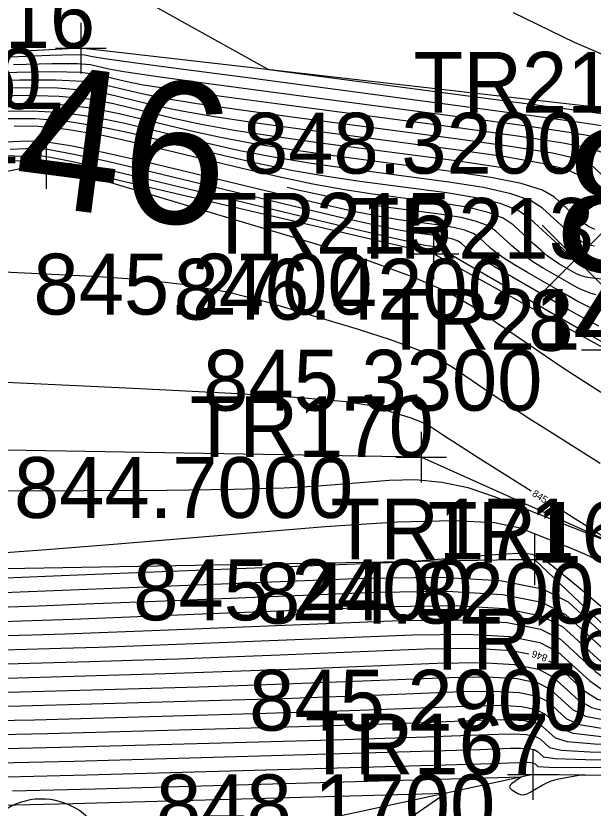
# Model space of a CAD drawing. Extents: x 1654928 to 1810050, y 486881 to 626330.
# Drawn here: x 1801337.91 to 1801349.3, y 489780.62 to 489796.25 of the extents above; entities that cross this region are included whole.
import ezdxf

# ---------------------------------------------------------------- set-up
doc = ezdxf.new("R2010")
doc.units = 0
for name, color, linetype in [('DR_X_Ditch', 7, 'Continuous'), ('DT_X_Contour_Major', 7, 'Continuous'), ('DT_X_Contour_Minor', 7, 'Continuous'), ('SV_X_Random_Point', 7, 'Continuous'), ('SV_X_Shot_Marker', 7, 'Continuous'), ('SV_X_Text_Elevation', 7, 'Continuous'), ('SV_X_Text_Name', 7, 'Continuous'), ('SV_X_Toe_of_Slope', 7, 'Continuous'), ('SV_X_Top_of_Bank', 7, 'Continuous'), ('VG_X_Cells', 7, 'Continuous')]:
    doc.layers.add(name, color=color, linetype=linetype)

msp = doc.modelspace()

# ---------------------------------------------------------------- linework, layer by layer
at = {"layer": 'DR_X_Ditch'}
msp.add_lwpolyline([(1801415.613, 489805.461), (1801399.12, 489798.656), (1801394.115, 489798.231), (1801381.169, 489793.34), (1801378.227, 489791.154), (1801376.864, 489788.486), (1801373.817, 489786.687), (1801350.547, 489785.463), (1801345.905, 489787.547), (1801327.981, 489787.847), (1801322.506, 489787.279)], dxfattribs=at)
at = {"layer": 'DT_X_Contour_Major'}
for points in [[(1801349.723, 489794.04), (1801349.121, 489794.135), (1801348.139, 489794.274), (1801346.777, 489794.457), (1801342.637, 489795.005), (1801341.272, 489795.186), (1801340.281, 489795.319), (1801339.664, 489795.404), (1801339.421, 489795.442), (1801339.272, 489795.478), (1801339.072, 489795.482), (1801338.583, 489795.469), (1801337.806, 489795.438)], [(1801347.859, 489793.184), (1801347.423, 489793.267), (1801346.546, 489793.396), (1801343.923, 489793.742), (1801343.005, 489793.87), (1801342.22, 489793.992), (1801341.568, 489794.109), (1801341.047, 489794.221), (1801339.837, 489794.513), (1801339.342, 489794.604), (1801338.767, 489794.659), (1801338.11, 489794.677), (1801337.372, 489794.658)], [(1801349.358, 489790.75), (1801349.263, 489790.771), (1801349.141, 489790.817), (1801348.992, 489790.888), (1801348.817, 489790.985), (1801348.312, 489791.276), (1801348.131, 489791.385), (1801347.969, 489791.495), (1801347.824, 489791.604), (1801347.697, 489791.713), (1801347.382, 489792.005), (1801347.227, 489792.108), (1801346.998, 489792.197), (1801346.694, 489792.272), (1801346.316, 489792.334), (1801345.209, 489792.48), (1801344.739, 489792.554), (1801344.16, 489792.665), (1801343.472, 489792.814), (1801343.265, 489792.862)], [(1801336.718, 489791.247), (1801339.433, 489791.119), (1801340.409, 489791.052), (1801341.302, 489790.945), (1801342.112, 489790.799), (1801342.838, 489790.614), (1801344.663, 489790.068), (1801345.293, 489789.868), (1801345.812, 489789.678), (1801346.22, 489789.498), (1801346.518, 489789.327), (1801347.165, 489788.886), (1801347.425, 489788.711), (1801347.721, 489788.517), (1801348.051, 489788.304), (1801348.416, 489788.072), (1801349.437, 489787.428)], [(1801355.714, 489785.207), (1801353.704, 489785.061), (1801352.39, 489784.954), (1801351.771, 489784.885), (1801351.048, 489784.753), (1801350.792, 489784.726), (1801350.567, 489784.742), (1801350.373, 489784.802), (1801350.209, 489784.906), (1801349.814, 489785.24), (1801349.639, 489785.367), (1801349.413, 489785.498), (1801349.136, 489785.633), (1801348.806, 489785.771), (1801347.859, 489786.145), (1801347.352, 489786.252), (1801346.543, 489786.291), (1801345.431, 489786.264), (1801344.016, 489786.169), (1801339.839, 489785.826), (1801338.431, 489785.714), (1801337.34, 489785.634)], [(1801336.723, 489784), (1801338.226, 489784.042), (1801338.884, 489784.062), (1801339.731, 489784.092), (1801340.765, 489784.131), (1801345.501, 489784.322), (1801346.686, 489784.339), (1801347.606, 489784.283), (1801348.262, 489784.154), (1801348.654, 489783.953), (1801349.346, 489783.319), (1801349.627, 489783.111), (1801349.95, 489782.964), (1801350.315, 489782.878), (1801350.723, 489782.853), (1801351.867, 489782.865), (1801352.39, 489782.865), (1801353.1, 489782.855), (1801353.998, 489782.836), (1801355.084, 489782.808)], [(1801336.934, 489782.622), (1801338.017, 489782.639), (1801342.183, 489782.757), (1801343.169, 489782.788), (1801344.045, 489782.818), (1801344.81, 489782.847), (1801346.704, 489782.924), (1801347.343, 489782.933), (1801347.839, 489782.903), (1801348.193, 489782.833), (1801348.404, 489782.725), (1801348.777, 489782.383), (1801349.029, 489782.272), (1801349.504, 489782.196), (1801350.202, 489782.155), (1801351.123, 489782.149), (1801353.878, 489782.179), (1801354.873, 489782.186), (1801355.79, 489782.186)], [(1801337.742, 489781.243), (1801339.312, 489781.279), (1801347.324, 489781.505), (1801347.632, 489781.515), (1801347.907, 489781.526), (1801348, 489781.527), (1801348.072, 489781.523), (1801348.123, 489781.513), (1801348.154, 489781.497), (1801348.208, 489781.447), (1801348.431, 489781.433), (1801349.057, 489781.428), (1801350.088, 489781.432), (1801351.523, 489781.446), (1801355.889, 489781.493)]]:
    msp.add_lwpolyline(points, dxfattribs=at)
at = {"layer": 'DT_X_Contour_Minor'}
for points in [[(1801355.691, 489793.524), (1801354.891, 489793.623), (1801352.455, 489793.925), (1801351.649, 489794.024), (1801351.059, 489794.095), (1801350.685, 489794.137), (1801350.526, 489794.151), (1801350.391, 489794.151), (1801350.345, 489794.151), (1801350.311, 489794.152), (1801350.286, 489794.152), (1801350.273, 489794.153), (1801350.25, 489794.155), (1801350.241, 489794.157), (1801350.232, 489794.162), (1801350.221, 489794.169), (1801350.21, 489794.179), (1801350.179, 489794.208), (1801350.032, 489794.235), (1801349.617, 489794.296), (1801348.933, 489794.39), (1801347.979, 489794.517), (1801342.902, 489795.188), (1801340.65, 489796.433)], [(1801355.223, 489795.998), (1801354.882, 489796.013), (1801354.491, 489796), (1801354.048, 489795.961), (1801352.798, 489795.82), (1801352.361, 489795.759), (1801351.987, 489795.682), (1801351.676, 489795.588), (1801351.428, 489795.478), (1801350.852, 489795.164), (1801350.494, 489795.148), (1801349.854, 489795.333), (1801348.932, 489795.722), (1801347.727, 489796.312)], [(1801349.486, 489793.836), (1801348.914, 489793.936), (1801347.996, 489794.073), (1801346.731, 489794.245), (1801342.894, 489794.752), (1801341.619, 489794.923), (1801340.669, 489795.054), (1801340.044, 489795.145), (1801339.746, 489795.198), (1801339.385, 489795.285), (1801339.126, 489795.307), (1801338.62, 489795.307), (1801337.867, 489795.286)], [(1801349.475, 489793.552), (1801349.248, 489793.631), (1801348.707, 489793.737), (1801347.853, 489793.871), (1801346.685, 489794.033), (1801343.152, 489794.5), (1801341.965, 489794.659), (1801341.057, 489794.788), (1801340.425, 489794.886), (1801340.071, 489794.954), (1801339.498, 489795.092), (1801339.18, 489795.131), (1801338.657, 489795.145), (1801337.928, 489795.133), (1801336.993, 489795.097)], [(1801349.481, 489793.111), (1801349.241, 489793.333), (1801349.011, 489793.426), (1801348.5, 489793.539), (1801347.71, 489793.67), (1801346.639, 489793.82), (1801343.409, 489794.247), (1801342.312, 489794.396), (1801341.444, 489794.523), (1801340.806, 489794.627), (1801340.397, 489794.709), (1801339.611, 489794.899), (1801339.234, 489794.955), (1801338.693, 489794.983), (1801337.988, 489794.981), (1801337.119, 489794.95)], [(1801349.405, 489792.754), (1801349.299, 489792.844), (1801349.007, 489793.115), (1801348.774, 489793.222), (1801348.294, 489793.34), (1801347.566, 489793.468), (1801346.592, 489793.608), (1801343.666, 489793.995), (1801342.659, 489794.133), (1801341.832, 489794.257), (1801341.187, 489794.368), (1801340.722, 489794.465), (1801339.724, 489794.706), (1801339.288, 489794.78), (1801338.73, 489794.821), (1801338.049, 489794.829), (1801337.246, 489794.804)], [(1801349.333, 489792.039), (1801349.211, 489792.097), (1801349.078, 489792.188), (1801348.934, 489792.31), (1801348.538, 489792.677), (1801348.299, 489792.813), (1801347.88, 489792.942), (1801347.28, 489793.065), (1801346.5, 489793.183), (1801344.18, 489793.49), (1801343.352, 489793.607), (1801342.608, 489793.727), (1801341.949, 489793.85), (1801341.373, 489793.977), (1801339.95, 489794.32), (1801339.396, 489794.429), (1801338.803, 489794.497), (1801338.171, 489794.524), (1801337.499, 489794.512)], [(1801349.329, 489791.706), (1801349.203, 489791.736), (1801349.065, 489791.802), (1801348.915, 489791.905), (1801348.752, 489792.043), (1801348.303, 489792.459), (1801348.062, 489792.608), (1801347.673, 489792.743), (1801347.137, 489792.864), (1801346.454, 489792.971), (1801344.437, 489793.237), (1801343.699, 489793.343), (1801342.996, 489793.461), (1801342.329, 489793.591), (1801341.698, 489793.733), (1801340.063, 489794.127), (1801339.45, 489794.253), (1801338.84, 489794.335), (1801338.232, 489794.372), (1801337.625, 489794.365)], [(1801349.578, 489791.363), (1801349.231, 489791.398), (1801349.117, 489791.41), (1801349.032, 489791.421), (1801348.977, 489791.429), (1801348.953, 489791.435), (1801348.929, 489791.449), (1801348.898, 489791.475), (1801348.824, 489791.541), (1801348.707, 489791.649), (1801348.546, 489791.798), (1801348.059, 489792.25), (1801347.818, 489792.409), (1801347.463, 489792.546), (1801346.993, 489792.663), (1801346.408, 489792.759), (1801344.695, 489792.985), (1801344.046, 489793.08), (1801343.384, 489793.196), (1801342.71, 489793.332), (1801342.023, 489793.489), (1801340.175, 489793.934), (1801339.504, 489794.077), (1801338.877, 489794.172), (1801338.293, 489794.22), (1801337.752, 489794.219)], [(1801349.577, 489791.045), (1801349.295, 489791.074), (1801349.19, 489791.09), (1801349.087, 489791.119), (1801348.985, 489791.158), (1801348.885, 489791.21), (1801348.62, 489791.362), (1801348.515, 489791.43), (1801348.396, 489791.518), (1801348.265, 489791.627), (1801348.121, 489791.756), (1801347.72, 489792.128), (1801347.523, 489792.258), (1801347.23, 489792.372), (1801346.844, 489792.468), (1801346.362, 489792.546), (1801344.952, 489792.733), (1801344.392, 489792.817), (1801343.772, 489792.931), (1801343.091, 489793.073), (1801342.349, 489793.245), (1801340.288, 489793.741), (1801339.558, 489793.902), (1801338.913, 489794.01), (1801338.353, 489794.067), (1801337.879, 489794.073)], [(1801349.337, 489790.451), (1801349.196, 489790.515), (1801349, 489790.618), (1801348.748, 489790.76), (1801348.003, 489791.19), (1801347.748, 489791.341), (1801347.541, 489791.471), (1801347.382, 489791.581), (1801347.272, 489791.671), (1801347.044, 489791.883), (1801346.931, 489791.957), (1801346.765, 489792.022), (1801346.544, 489792.077), (1801346.27, 489792.121), (1801345.466, 489792.228), (1801345.086, 489792.291), (1801344.548, 489792.4), (1801343.853, 489792.555), (1801342.999, 489792.757), (1801340.514, 489793.356), (1801339.666, 489793.551), (1801338.987, 489793.686), (1801338.475, 489793.763), (1801338.132, 489793.78), (1801337.44, 489793.747)], [(1801349.41, 489790.131), (1801349.251, 489790.213), (1801349.007, 489790.347), (1801348.68, 489790.534), (1801347.694, 489791.103), (1801347.364, 489791.296), (1801347.113, 489791.448), (1801346.941, 489791.559), (1801346.848, 489791.629), (1801346.706, 489791.761), (1801346.636, 489791.807), (1801346.532, 489791.847), (1801346.395, 489791.881), (1801346.224, 489791.909), (1801345.723, 489791.975), (1801345.433, 489792.027), (1801344.936, 489792.134), (1801344.233, 489792.296), (1801343.325, 489792.512), (1801340.627, 489793.163), (1801339.72, 489793.375), (1801339.023, 489793.524), (1801338.536, 489793.611), (1801338.258, 489793.634), (1801337.797, 489793.612)], [(1801349.483, 489789.811), (1801349.015, 489790.077), (1801346.98, 489791.251), (1801346.685, 489791.424), (1801346.499, 489791.536), (1801346.423, 489791.586), (1801346.367, 489791.638), (1801346.34, 489791.656), (1801346.299, 489791.672), (1801346.245, 489791.686), (1801346.178, 489791.697), (1801345.98, 489791.723), (1801345.779, 489791.764), (1801345.324, 489791.869), (1801344.614, 489792.037), (1801340.74, 489792.97), (1801339.774, 489793.199), (1801339.06, 489793.362), (1801338.597, 489793.458), (1801338.385, 489793.488), (1801338.154, 489793.477), (1801338.011, 489793.477), (1801337.754, 489793.487)], [(1801364.304, 489787.262), (1801363.958, 489787.248), (1801358.689, 489787.046), (1801356.868, 489787.012), (1801355.356, 489787.06), (1801354.154, 489787.191), (1801353.262, 489787.404), (1801351.295, 489788.083), (1801350.63, 489788.318), (1801350.113, 489788.513), (1801349.742, 489788.668), (1801349.518, 489788.783), (1801349.116, 489789.036), (1801348.933, 489789.154), (1801348.687, 489789.317), (1801348.378, 489789.525), (1801348.005, 489789.778), (1801346.927, 489790.514), (1801346.43, 489790.798), (1801345.75, 489791.099), (1801344.885, 489791.415), (1801343.836, 489791.749), (1801338.511, 489793.341), (1801332.343, 489792.068)], [(1801334.925, 489789.154), (1801340.354, 489788.898), (1801342.164, 489788.805), (1801343.522, 489788.72), (1801344.428, 489788.641), (1801344.883, 489788.569), (1801345.491, 489788.387), (1801345.701, 489788.321), (1801345.874, 489788.257), (1801346.01, 489788.197), (1801346.109, 489788.14), (1801346.325, 489787.993), (1801346.457, 489787.906), (1801346.693, 489787.755), (1801347.031, 489787.54), (1801348.078, 489786.88)], [(1801348.433, 489786.656), (1801349.773, 489785.81), (1801347.356, 489786.764), (1801346.837, 489786.938), (1801346.317, 489787.049), (1801345.797, 489787.099), (1801345.275, 489787.087), (1801343.883, 489786.973), (1801343.202, 489786.936), (1801342.202, 489786.908), (1801340.883, 489786.89), (1801339.247, 489786.882), (1801334.457, 489786.875)], [(1801337.714, 489785.165), (1801338.971, 489785.216), (1801345.61, 489785.484), (1801347.267, 489785.62), (1801347.585, 489785.642), (1801347.829, 489785.652), (1801348, 489785.648), (1801348.096, 489785.631), (1801348.254, 489785.569), (1801348.345, 489785.515), (1801348.499, 489785.401), (1801348.717, 489785.227), (1801348.998, 489784.992), (1801349.834, 489784.286), (1801350.179, 489784.067), (1801350.589, 489783.941), (1801351.065, 489783.907), (1801351.605, 489783.965), (1801353.131, 489784.243), (1801353.923, 489784.353), (1801355.153, 489784.477)], [(1801337.667, 489784.875), (1801344.779, 489785.161), (1801346.291, 489785.182), (1801347.466, 489785.111), (1801348.304, 489784.947), (1801348.804, 489784.69), (1801349.688, 489783.88), (1801349.986, 489783.615), (1801350.218, 489783.425), (1801350.384, 489783.312), (1801350.483, 489783.275), (1801350.75, 489783.276), (1801351.294, 489783.264), (1801352.463, 489783.231), (1801355.106, 489783.712)], [(1801337.565, 489784.585), (1801338.355, 489784.614), (1801339.453, 489784.657), (1801340.859, 489784.713), (1801345.019, 489784.881), (1801346.423, 489784.901), (1801347.513, 489784.835), (1801348.29, 489784.683), (1801348.754, 489784.444), (1801349.574, 489783.693), (1801349.866, 489783.447), (1801350.129, 489783.272), (1801350.361, 489783.167), (1801350.563, 489783.134), (1801351.063, 489783.139), (1801351.315, 489783.139), (1801351.696, 489783.132), (1801352.208, 489783.121), (1801352.848, 489783.104), (1801356.142, 489783.011)], [(1801337.654, 489784.305), (1801338.224, 489784.323), (1801339.043, 489784.353), (1801341.424, 489784.447), (1801345.26, 489784.602), (1801346.554, 489784.62), (1801347.56, 489784.559), (1801348.276, 489784.418), (1801348.704, 489784.198), (1801349.46, 489783.506), (1801349.747, 489783.279), (1801350.039, 489783.118), (1801350.338, 489783.023), (1801350.643, 489782.993), (1801351.465, 489783.002), (1801351.879, 489783.001), (1801352.507, 489782.991), (1801353.348, 489782.972), (1801354.403, 489782.943), (1801359.821, 489782.79)], [(1801336.981, 489783.728), (1801338.798, 489783.779), (1801339.544, 489783.801), (1801340.418, 489783.831), (1801341.421, 489783.869), (1801345.741, 489784.042), (1801346.817, 489784.058), (1801347.653, 489784.007), (1801348.248, 489783.89), (1801348.604, 489783.707), (1801349.232, 489783.132), (1801349.507, 489782.943), (1801349.861, 489782.811), (1801350.293, 489782.734), (1801350.803, 489782.712), (1801352.269, 489782.728), (1801352.886, 489782.729), (1801353.638, 489782.721), (1801354.525, 489782.704), (1801355.546, 489782.678)], [(1801337.24, 489783.456), (1801339.371, 489783.515), (1801340.204, 489783.54), (1801341.106, 489783.571), (1801342.077, 489783.606), (1801343.117, 489783.647), (1801345.982, 489783.763), (1801346.948, 489783.776), (1801347.699, 489783.731), (1801348.029, 489783.666)], [(1801348.422, 489783.53), (1801348.554, 489783.462), (1801349.119, 489782.944), (1801349.388, 489782.776), (1801349.771, 489782.657), (1801350.27, 489782.589), (1801350.883, 489782.571), (1801352.671, 489782.591), (1801353.383, 489782.593), (1801354.176, 489782.588), (1801355.051, 489782.573), (1801356.008, 489782.549)], [(1801337.499, 489783.183), (1801339.943, 489783.252), (1801340.864, 489783.279), (1801341.794, 489783.31), (1801342.733, 489783.343), (1801343.681, 489783.38), (1801346.223, 489783.483), (1801347.08, 489783.495), (1801347.746, 489783.455), (1801348.221, 489783.362), (1801348.504, 489783.216), (1801349.005, 489782.757), (1801349.268, 489782.608), (1801349.682, 489782.504), (1801350.247, 489782.444), (1801350.963, 489782.43), (1801353.074, 489782.453), (1801353.879, 489782.458), (1801354.714, 489782.454), (1801355.578, 489782.441)], [(1801337.758, 489782.911), (1801341.523, 489783.018), (1801342.481, 489783.049), (1801343.389, 489783.081), (1801344.246, 489783.114), (1801346.463, 489783.203), (1801347.211, 489783.214), (1801347.792, 489783.179), (1801348.207, 489783.098), (1801348.454, 489782.97), (1801348.891, 489782.57), (1801349.148, 489782.44), (1801349.593, 489782.35), (1801350.224, 489782.3), (1801351.043, 489782.29), (1801353.476, 489782.316), (1801354.376, 489782.322), (1801355.252, 489782.32)], [(1801337.096, 489782.346), (1801338.276, 489782.367), (1801342.843, 489782.496), (1801343.857, 489782.527), (1801344.701, 489782.555), (1801345.374, 489782.581), (1801346.944, 489782.644), (1801347.474, 489782.652), (1801347.886, 489782.627), (1801348.179, 489782.569), (1801348.354, 489782.479), (1801348.663, 489782.196), (1801348.909, 489782.104), (1801349.414, 489782.043), (1801350.179, 489782.011), (1801351.203, 489782.008), (1801354.28, 489782.042), (1801355.369, 489782.051)], [(1801337.258, 489782.071), (1801338.535, 489782.095), (1801343.503, 489782.235), (1801344.545, 489782.266), (1801345.356, 489782.293), (1801345.939, 489782.314), (1801347.185, 489782.365), (1801347.606, 489782.371), (1801347.932, 489782.351), (1801348.165, 489782.305), (1801348.304, 489782.234), (1801348.55, 489782.009), (1801348.79, 489781.936), (1801349.325, 489781.889), (1801350.156, 489781.866), (1801351.283, 489781.868), (1801354.682, 489781.905), (1801355.866, 489781.915)], [(1801337.419, 489781.795), (1801338.794, 489781.823), (1801344.163, 489781.974), (1801346.012, 489782.03), (1801346.503, 489782.048), (1801347.426, 489782.085), (1801347.737, 489782.089), (1801347.979, 489782.075), (1801348.151, 489782.041), (1801348.254, 489781.988), (1801348.436, 489781.821), (1801348.67, 489781.769), (1801349.236, 489781.735), (1801350.134, 489781.721), (1801351.363, 489781.727), (1801355.085, 489781.768)], [(1801337.581, 489781.519), (1801339.053, 489781.551), (1801345.92, 489781.745), (1801347.067, 489781.781), (1801347.666, 489781.805), (1801347.868, 489781.808), (1801348.025, 489781.799), (1801348.137, 489781.777), (1801348.204, 489781.742), (1801348.322, 489781.634), (1801348.55, 489781.601), (1801349.147, 489781.582), (1801350.111, 489781.577), (1801351.443, 489781.586), (1801355.487, 489781.63)], [(1801337.846, 489780.966), (1801339.468, 489781.004), (1801347.888, 489781.24), (1801347.691, 489781.103), (1801347.66, 489781.074), (1801347.65, 489781.045), (1801347.663, 489781.016), (1801347.697, 489780.987), (1801347.817, 489780.909), (1801347.867, 489780.89), (1801347.926, 489780.889), (1801347.995, 489780.908), (1801348.072, 489780.947), (1801348.293, 489781.075), (1801348.375, 489781.119), (1801348.458, 489781.155), (1801348.542, 489781.183), (1801348.625, 489781.203), (1801349.017, 489781.277), (1801358.009, 489781.374)], [(1801337.62, 489780.679), (1801339.038, 489780.712), (1801346.399, 489780.919), (1801344.889, 489779.872)]]:
    msp.add_lwpolyline(points, dxfattribs=at)
at = {"layer": 'SV_X_Random_Point'}
for p, q in [((1801348.293, 489790.79), (1801349.627, 489792.125)), ((1801348.293, 489792.125), (1801349.627, 489790.79))]:
    msp.add_line(p, q, dxfattribs=at)
at = {"layer": 'SV_X_Shot_Marker'}
for p, q in [((1801339.193, 489796.113), (1801339.193, 489795.113)), ((1801338.693, 489795.613), (1801339.693, 489795.613)), ((1801339.193, 489795.613), (1801339.193, 489795.613)), ((1801338.511, 489793.841), (1801338.511, 489792.841)), ((1801338.011, 489793.341), (1801339.011, 489793.341)), ((1801338.511, 489793.341), (1801338.511, 489793.341)), ((1801346.148, 489792.059), (1801346.148, 489791.059)), ((1801345.648, 489791.559), (1801346.648, 489791.559)), ((1801346.148, 489791.559), (1801346.148, 489791.559)), ((1801349.07, 489789.663), (1801350.07, 489789.663)), ((1801345.905, 489788.047), (1801345.905, 489787.047)), ((1801345.405, 489787.547), (1801346.405, 489787.547)), ((1801345.905, 489787.547), (1801345.905, 489787.547)), ((1801348.143, 489786.028), (1801348.143, 489785.028)), ((1801347.643, 489785.528), (1801348.643, 489785.528)), ((1801348.143, 489785.528), (1801348.143, 489785.528)), ((1801348.111, 489781.788), (1801348.111, 489780.788)), ((1801347.611, 489781.288), (1801348.611, 489781.288)), ((1801348.111, 489781.288), (1801348.111, 489781.288))]:
    msp.add_line(p, q, dxfattribs=at)
at = {"layer": 'SV_X_Toe_of_Slope'}
for points in [[(1801412.543, 489809.732), (1801392.991, 489804.275), (1801388.448, 489803.512), (1801377.572, 489796.441), (1801374.044, 489792.616), (1801367.753, 489789.382), (1801359.258, 489788.44), (1801349.57, 489789.663), (1801346.148, 489791.559), (1801338.511, 489793.341), (1801330.855, 489793.994), (1801326.103, 489791.66), (1801319.382, 489791.876), (1801317.575, 489794.338), (1801316.785, 489794.599)], [(1801417.791, 489799.995), (1801412.832, 489796.754), (1801412.089, 489795.17), (1801401.953, 489790.438), (1801397.863, 489793.263), (1801395.881, 489794.687), (1801394.491, 489796.208), (1801381.141, 489790.72), (1801379.18, 489788.057), (1801375.237, 489785.681), (1801360.556, 489782.746), (1801350.439, 489783.352), (1801348.143, 489785.528), (1801335.479, 489785.306), (1801328.907, 489786.007), (1801321.924, 489784.909)]]:
    msp.add_lwpolyline(points, dxfattribs=at)
at = {"layer": 'SV_X_Top_of_Bank'}
for points in [[(1801422.074, 489809.374), (1801419.071, 489811.095), (1801415.847, 489811.951), (1801411.348, 489810.567), (1801392.1, 489806.2), (1801386.944, 489805.19), (1801377.801, 489798.251), (1801372.871, 489798.042), (1801363.859, 489794.96), (1801356.721, 489793.409), (1801350.319, 489794.339), (1801339.193, 489795.613), (1801330.88, 489795.172), (1801318.326, 489796.108)], [(1801414.708, 489795.331), (1801414.041, 489794.432), (1801412.967, 489794.649), (1801413.875, 489794.726), (1801401.963, 489788.753), (1801387.705, 489783.674), (1801376.875, 489783.007), (1801368.983, 489780.458), (1801361.095, 489781.125), (1801348.111, 489781.288), (1801336.05, 489778.687), (1801318.855, 489781.567)]]:
    msp.add_lwpolyline(points, dxfattribs=at)
at = {"layer": 'VG_X_Cells'}
msp.add_arc((1801338.421, 489779.487), 1.317, 354.0047, 205.9741, dxfattribs=at)

# ---------------------------------------------------------------- texts
at = {"layer": 'DT_X_Contour_Major'}
for s, rotation, p in [('846', 352.5909, (1801335.736, 489792.842)), ('847', 351.5707, (1801348.437, 489791.361))]:
    msp.add_text(s, height=2.8, rotation=rotation, dxfattribs=at).set_placement(p)
at = {"layer": 'DT_X_Contour_Minor'}
for s, rotation, p in [('845', 327.7595, (1801348.083, 489786.794)), ('846', 160.8357, (1801348.413, 489783.638))]:
    msp.add_text(s, height=0.14, rotation=rotation, dxfattribs=at).set_placement(p)
at = {"layer": 'SV_X_Text_Elevation'}
for s, p in [('848.1400', (1801331.73, 489794.413)), ('848.3200', (1801342.392, 489793.139)), ('845.2700', (1801338.258, 489790.359)), ('846.4200', (1801341.024, 489790.258)), ('846.0800', (1801348.019, 489789.644)), ('845.3300', (1801341.606, 489788.463)), ('844.7000', (1801337.874, 489786.347)), ('845.2400', (1801340.226, 489784.328)), ('844.8200', (1801342.63, 489784.263)), ('845.2900', (1801342.512, 489782.152)), ('848.1700', (1801340.676, 489780.088))]:
    msp.add_text(s, height=1.2, dxfattribs=at).set_placement(p)
at = {"layer": 'SV_X_Text_Name'}
for s, p in [('TR216', (1801334.659, 489795.613)), ('TR210', (1801345.757, 489794.339)), ('TR217', (1801334.052, 489793.341)), ('TR215', (1801341.689, 489791.559)), ('TR213', (1801344.501, 489791.458)), ('TR214', (1801345.121, 489789.663)), ('TR170', (1801341.342, 489787.547)), ('TR171', (1801344.118, 489785.528)), ('TR169', (1801346.041, 489785.463)), ('TR168', (1801345.933, 489783.352)), ('TR167', (1801343.615, 489781.288))]:
    msp.add_text(s, height=1.2, dxfattribs=at).set_placement(p)

doc.saveas('drawing.dxf')
